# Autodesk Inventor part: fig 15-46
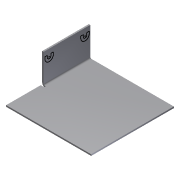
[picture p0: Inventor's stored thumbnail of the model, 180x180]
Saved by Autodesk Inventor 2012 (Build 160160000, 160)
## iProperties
Created: 2005-03
Part Number: fig 15-46
Document SubType Name: Sheet Metal
Designer: CADCIM
Manufacturer: Standard
Standards Organization: Custom
Density: 1 g/cm^3
Sheet Metal Rule: Default
Material: Default
Author: CADCIM
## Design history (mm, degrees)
node "Face1"
  sketch "Sketch1"
    geometry: L1 (-29, -26)-(30, -26); L2 (30, -26)-(30, 31.375); L3 (30, 31.375)-(-29, 31.375); L4 (-29, 31.375)-(-29, -26)
    constraints: 8 end point, 2 parallel, 1 horizontal, 1 perpendicular
node "Flange1"
sketch "Sketch4"
  geometry: L1 (3.278, 0.812)-(4.721, 0.812); L2 (4.721, 6.681)-(3.278, 6.681); L3 (3.278, 4.946)-(4.721, 4.946); L4 (4.721, 2.546)-(3.278, 2.546); L5 (3.278, 0.812)-(3.278, 2.546); L6 (3.278, 4.946)-(3.278, 6.681); L7 (3.278, 31.563)-(4.721, 31.563); L8 (4.721, 25.694)-(3.278, 25.694); L9 (3.278, 27.429)-(4.721, 27.429); L10 (4.721, 29.829)-(3.278, 29.829); L11 (3.278, 31.563)-(3.278, 29.829); L12 (3.278, 27.429)-(3.278, 25.694); A1 r 2.935 centre (4.721, 3.746) between (4.721, 0.812) and (4.721, 6.681); A2 r 1.2 centre (4.721, 3.746) between (4.721, 2.546) and (4.721, 4.946); A3 r 2.935 centre (4.721, 28.629) between (4.721, 25.694) and (4.721, 31.563); A4 r 1.2 centre (4.721, 28.629) between (4.721, 27.429) and (4.721, 29.829)
  constraints: 24 end point, 8 point on circle, 4 centre point, 3 equal length, 2 tangent, 1 horizontal, 1 perpendicular, 1 vertical alignment, 2 other
body "Solid1"
face "Plate1" dims "Thickness" = 1
sketch "Sketch2"
  geometry: L1 (25, 0)-(57.375, 0); L2 (57.375, 0)-(57.375, 20); L3 (57.375, 20)-(25, 20); L4 (25, 20)-(25, 0)
  constraints: 8 end point
face "Plate2" dims "d1" = 0, "d2" = 25, "d3" = 1 (= BendReliefWidth), "d5" = 2 (= MinimumRemnant), "d7" = 20, "d8" = 90 deg, "d9" = 1 (= BendRadius), "Thickness" = 1
bend "Bend1" dims "d3" = 1 (= BendReliefWidth), "d4" = 0.5 (= BendReliefDepth), "d5" = 2 (= MinimumRemnant), "d6" = 1 (= BendRadius), "d7" = 20, "d8" = 90 deg, "d9" = 1 (= BendRadius), "SeamGap" = 0.01, "Thickness" = 1
other parameters: "BendRadius" = 1 (= Thickness), "BendReliefWidth" = 1 (= Thickness), "BendReliefDepth" = 0.5 (= 0.5 x Thickness), "CornerReliefSize" = 4 (= 4 x Thickness), "MinimumRemnant" = 2 (= 2 x Thickness), "TransitionRadius" = 1 (= BendRadius), "d0" = 1 (= BendRadius), "JacobiRadiusSize" = 1 (= Thickness), "GapSize" = 1 (= Thickness)
